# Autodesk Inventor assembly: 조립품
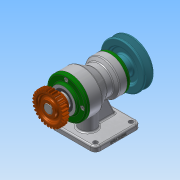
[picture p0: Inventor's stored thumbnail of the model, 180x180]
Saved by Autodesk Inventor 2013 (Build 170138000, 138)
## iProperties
Created: 2019-01
Part Number: 조립품
Document SubType Name: Assembly
Designer: Administrator
Author: Administrator
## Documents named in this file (15)
- C:\Users\Administrator\Desktop\490107V1024\조립품.iam
- C:\Users\Administrator\Desktop\490107V1024\본체.ipt
- C:\Users\Administrator\Desktop\490107V1024\축.ipt
- C:\Users\Administrator\Desktop\490107V1024\베어링 6203.ipt
- C:\Users\Administrator\Desktop\490107V1024\베어링 6205.ipt
- C:\Users\Administrator\Desktop\490107V1024\오일 실 17 30 8.ipt
- C:\Users\Administrator\Desktop\490107V1024\오일 실 25 38 8.ipt
- C:\Users\Administrator\Desktop\490107V1024\뒤커버.ipt
- C:\Users\Administrator\Desktop\490107V1024\앞커버.ipt
- C:\Users\Administrator\Desktop\490107V1024\V-벨트풀리.ipt
- C:\Users\Administrator\Desktop\490107V1024\멈춤나사 M3.ipt
- C:\Users\Administrator\Desktop\490107V1024\키 5 x 5 x 20.ipt
- C:\Users\Administrator\Desktop\490107V1024\스퍼기어.ipt
- C:\Users\Administrator\Desktop\490107V1024\키 6 x 6 x 18.ipt
- C:\Users\Administrator\Desktop\490107V1024\볼트 M4.ipt
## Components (1 placed, 1 different names)
1. V-벨트풀리:1 — 각도:1, 플러쉬:1
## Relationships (2: Angle 1, Flush 1)
- 각도:1 [Angle]: V-벨트풀리:1
- 플러쉬:1 [Flush]: V-벨트풀리:1
